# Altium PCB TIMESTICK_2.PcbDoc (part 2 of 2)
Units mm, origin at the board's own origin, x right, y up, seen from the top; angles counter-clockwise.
Board outline 82 x 42 mm, 4 copper layers (Top Layer, Int1, Int2, Bottom Layer), stack 0.954 mm thick; 117 components, 82 nets, 437 pads, 366 vias.
Unrouted connection lines stored in the file: 51.
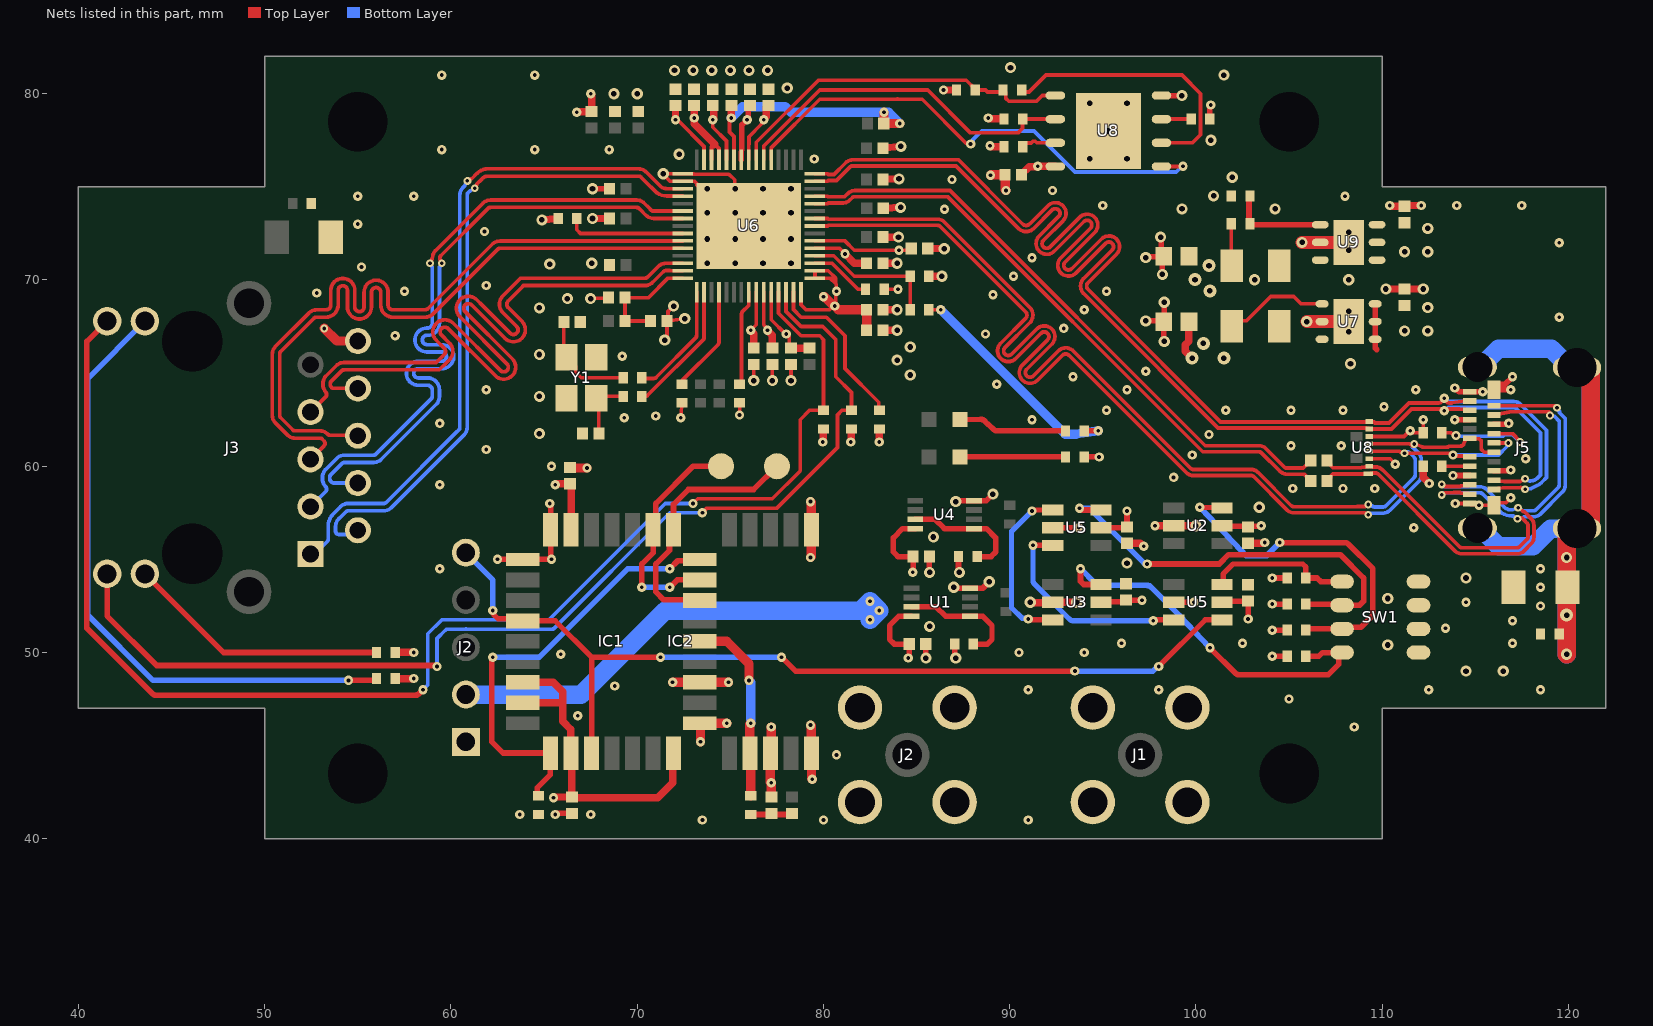
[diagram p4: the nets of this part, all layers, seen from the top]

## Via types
v1: diameter 0.5, hole 0.2, Top Layer to Bottom Layer, tented both sides, 226 vias
v2: diameter 0.6, hole 0.3, Top Layer to Bottom Layer, tented both sides, 105 vias
v3: diameter 0.42, hole 0.2, Top Layer to Bottom Layer, tented both sides, 19 vias
v4: diameter 0.6, hole 0.3, Top Layer to Bottom Layer, 9 vias
v5: diameter 0.7, hole 0.3, Top Layer to Bottom Layer, tented both sides, 7 vias

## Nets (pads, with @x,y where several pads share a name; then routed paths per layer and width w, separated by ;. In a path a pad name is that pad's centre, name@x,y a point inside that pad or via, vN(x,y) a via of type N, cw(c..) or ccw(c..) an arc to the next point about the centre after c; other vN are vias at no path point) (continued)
D_N: J5.A7 J5.B7 U6.38 U8.5@109.3,61.2 | length 58.9
  Top Layer w0.2: U6.38@79.541,72.9 80.215,72.9 80.253,72.937 85.985,72.937 86.12,72.937 cw(c86.12,72.737) 86.261,72.879 87.563,71.577 89.37,69.77 90.17,68.97 90.85,68.29 ; 90.329,65.787 cw(c89.922,66.193) 89.515,65.787 cw(c89.922,66.193) 89.515,66.6 90.851,67.936 ccw(c90.674,68.112) 90.851,68.29 ; 90.33,65.788 91.678,67.137 cw(c91.855,66.96) 92.033,66.784 90.682,65.433 ccw(c91.089,65.027) 90.682,64.62 ccw(c91.089,65.027) 91.496,64.621 ; 91.496,64.621 92.831,65.956 cw(c93.008,65.779) 93.185,65.955 93.37,65.77 99.489,59.652 ccw(c99.858,60.025) 99.858,59.5 102.823,59.5 102.958,59.5 cw(c102.958,59.3) 103.099,59.441 104.887,57.654 ccw(c105.258,58.025) 105.258,57.5 108.785,57.5 108.792,57.507 109.073,57.507 109.19,57.39 v3(109.25,57.39) ; U8.5@109.3,61.2 111.478,61.2 111.608,61.07 v3(111.726,61.187) 111.845,61.147 cw(c111.779,60.958) 111.847,61.146 112.15,61.037 ccw(c112.217,61.225) 112.217,61.025 113.472,61.025 ccw(c113.471,61.225) 113.603,61.075 113.888,61.075 ccw(c113.888,61.275) 113.895,61.075 113.956,61.077 cw(c113.962,60.877) 113.962,61.077 114.191,61.077 ccw(c114.191,61.277) 114.375,61.2 114.479,61.45 J5.A7@114.7,61.5 114.725,61.475 115.2,61.475 115.325,61.35 115.325,60.9 115.475,60.75 J5.B7@116,60.75
  Bottom Layer w0.2: v3(109.25,57.39) 109.277,57.417 109.335,57.475 109.999,57.475 110.087,57.475 110.155,57.498 110.194,57.509 ccw(c110.058,58.016) 110.428,57.643 110.532,57.747 111.947,59.163 ccw(c111.576,59.534) 112.101,59.534 112.101,60.341 ccw(c111.576,60.341) 111.948,60.712 111.71,60.949 ccw(c111.339,60.578) 111.62,61.021 111.726,61.127 v3(111.726,61.187)
D_P: J5.A6 J5.B6 U6.39 U8.4@109.3,60.8 | length 60.1
  Top Layer w0.2: U6.39@79.541,73.3 80.215,73.3 80.253,73.262 86.12,73.262 cw(c86.12,72.737) 86.49,73.11 90.4,69.2 91.081,68.519 ; 91.082,68.518 91.129,68.471 91.129,68.465 cw(c90.674,68.112) 91.081,67.706 89.745,66.37 ccw(c89.922,66.193) 89.745,66.017 ccw(c89.922,66.193) 90.098,66.016 91.449,67.366 cw(c91.855,66.96) 92.208,67.414 92.214,67.414 92.261,67.367 cw(c91.855,66.96) 92.262,67.366 92.309,67.319 92.309,67.313 cw(c91.855,66.96) 92.261,66.553 ; 92.261,66.552 90.912,65.204 ccw(c91.089,65.027) 90.912,64.85 ccw(c91.089,65.027) 91.265,64.849 92.601,66.186 cw(c93.008,65.779) 93.36,66.233 93.367,66.233 93.414,66.186 ; 93.414,66.186 93.6,66 99.717,59.883 ccw(c99.858,60.025) 99.858,59.825 102.958,59.825 cw(c102.958,59.3) 103.329,59.671 105.117,57.883 ccw(c105.258,58.025) 105.258,57.825 108.65,57.825 108.657,57.832 109.073,57.832 109.19,57.95 v3(109.25,57.95) ; U8.4@109.3,60.8 110.933,60.8 110.975,60.757 111.143,60.757 v3@111.21,60.69 ; v3(111.2,60.7) 113.617,60.7 cw(c113.617,60.5) 113.758,60.642 v1(113.8,60.6) 113.848,60.552 114.129,60.552 114.131,60.55 114.65,60.55 J5.A6@114.7,60.5 ; J5.B6@116,61.25 v3(116.775,61.25)
  Bottom Layer w0.2: v3(109.25,57.95) 109.44,57.865 109.447,57.865 109.453,57.859 109.51,57.833 ccw(c109.592,58.016) 109.592,57.816 110.058,57.816 ccw(c110.058,58.016) 110.199,57.874 111.717,59.392 ccw(c111.576,59.534) 111.776,59.534 111.776,59.937 111.776,60.341 ccw(c111.576,60.341) 111.717,60.483 111.481,60.719 ccw(c111.339,60.578) 111.339,60.778 111.262,60.7 v3(111.2,60.7) ; v1(113.8,60.6) 116.25,60.6 116.718,61.068 116.718,61.193 v3(116.775,61.25)
DVDD_1.85: C16.2 C30.2 C31.2 C32.2 FB4.1 U6.26 U6.35 U6.53 U6.56 | length 14.2
  Top Layer w0.2: v1(74.056,78.6) 74.056,78.2 74.791,77.465 U6.56@74.791,76.45 ; U6.53@75.991,76.45 75.991,77.302 75.996,77.307 75.996,77.696 76.661,78.361 76.661,78.38 76.8,78.519 v1(76.8,78.6) ; U6.26@77.191,69.35 77.191,67.865 77.956,67.1 v1(78,67.1) 78,67.093 78.156,66.937 78.156,66.44 C31.2@78.256,66.34 ; U6.35@79.541,71.7 80.856,71.7 v1(81.156,71.4)
  Top Layer w0.4: v1(74.056,78.6) 74.056,78.605 74.117,78.667 74.117,79.299 C16.2@74.056,79.36 ; v1(76.8,78.6) 76.8,78.627 76.938,78.765 76.938,79.26 77.038,79.36 C32.2@77.056,79.36 ; C31.2@78.256,66.34 FB4.1@79.256,66.34 ; v1(81.156,71.4) 81.656,70.9 C30.2@82.316,70.9
DVDD_33: C10.2 C14.2 C19.2 C20.2 C21.2 C22.2 C43.2 C44.2 FB3.1 IC1.7 IC1.8 IC2.2 IC2.7 IC2.23 L1.2 R10.2 R11.2 R14.2@75.5,63.4 R16.1 R17.1 R19.2 R20.2 R21.2 R27.1 R28.1@89.694,78.65 R29.1 R30.1@100.744,78.65 U6.25 U6.36 U6.54 U6.59 U7.1 U8.8@92.45,76.095 | length 59.2
  Top Layer w0.2: v1@71.956,78.7 71.956,79.26 C21.2@72.056,79.36 ; v1(72.056,78.6) 72.156,78.6 72.156,78.56 72.157,78.558 72.198,78.558 73.591,77.165 U6.59@73.591,76.45 ; v1(72.344,62.6) 72.39,63.25 R20.2@72.4,63.4 ; v1(75.494,62.75) 75.499,63.25 R14.2@75.5,63.4 ; U6.25@76.791,69.35 76.791,67.59 77,67.381 v1(77,67.3) ; U6.36@79.541,72.1 81.156,72.1 81.656,71.6 v1(84.056,71.6) 84.616,71.6 C20.2@84.716,71.7 ; R21.2@83.256,69.5 v1(84,69.5) ; L1.2@101.925,67.517 102.216,67.808 102.708,67.808 104.017,69.117 105.25,69.117 105.65,68.717 U7.1@106.775,68.717
  Top Layer w0.3: U6.54@75.591,76.45 75.616,77.41 75.621,77.477 75.621,78.324 75.897,78.6 v1(75.9,78.6) 75.9,78.654 75.959,78.713 75.959,79.263 C22.2@76.056,79.36 ; R30.1@100.744,78.65 100.744,79.312 100.8,79.368 v1(100.8,79.4)
  Top Layer w0.4: R10.2@57,48.6 v1(58,48.6) ; R11.2@57,50 v1(58,50) ; IC1.8@63.85,47.3 66,47.3 ; IC1.7@63.85,48.4 65.5,48.4 66,47.9 66,47.3 ; v1(65.5,42.2) 65.527,42.2 65.567,42.24 C43.2@66.5,42.24 ; v1(65.6,59) 65.627,59 65.687,59.06 C44.2@66.4,59.06 66.45,59.01 IC2.23@66.45,56.6 ; v1(66.75,79) 66.777,79 66.817,79.04 FB3.1@67.556,79.04 67.556,79.917 67.5,79.973 v1(67.5,80) ; IC2.7@71.95,44.6 71.9,44.55 71.9,43 71.1,42.2 66.54,42.2 C43.2@66.5,42.24 ; v1(72.056,78.6) C21.2@72.056,79.36 ; v1(77,67.3) 77,67.273 77.244,67.028 77.244,66.44 77.256,66.429 C19.2@77.256,66.34 ; v1(79.965,61.3) 79.965,61.305 80,61.341 R16.1@80,62 ; v1(81.465,61.3) 81.465,61.305 81.5,61.341 R17.1@81.5,62 ; v1(83,61.3) R19.2@83,62 ; v1(86.444,80.2) R27.1@87.144,80.2 ; v1(88.844,78.7) 88.85,78.7 88.9,78.65 R28.1@89.694,78.65 ; v1(88.944,77.2) 88.95,77.2 89,77.15 R29.1@89.694,77.15 ; C14.2@90.634,75.65 90.634,75.67 91.045,76.081 91.454,76.081 91.468,76.095 U8.8@92.45,76.095 ; C10.2@99.625,67.767 99.625,66.706 99.435,66.516 99.435,66.184 99.8,65.819 v5(99.8,65.8) ; 66,47.3 66,46.3 66.434,45.866 66.434,44.616 66.475,44.575 66.475,42.265 C43.2@66.5,42.24
  other v1: 91.5,76.1
  other v5: 101.5,65.8 100.4,66.6
GND: C1.1 C2.1 C3.1 C4.1 C5.1 C8.1 C9.1 C10.1 C11.1 C12.1 C13.1 C14.1 C15.1 C16.1 C17.1 C18.1 C19.1 C20.1 C21.1 C22.1 C23.1 C24.1 C25.1 C26.1 C27.1 C28.1 C29.1 C30.1 C31.1 C32.1 C33.1 C34.1 C35.1 C36.1 C37.1 C38.1 C39.2 C40.1 C42.1 C43.1 C44.1 IC1.1 IC1.10 IC1.12 IC2.10 IC2.12 IC2.13 IC2.24 J1.2 J1.3 J1.4 J1.5 J2.1@60.8,45.2 J2.2@87.04,41.96 J2.3@81.96,41.96 J2.4@81.96,47.04 J2.5@87.04,47.04 J3.P10 J5.A1 J5.A12 J5.B1 J5.B12 R1.2 R7.1 R12.2 R14.2@64.7,41.3 R15.1 R18.1 R24.1 R28.2@112.2,60 R30.2@112.2,61.8 R33.2 SW1.1 SW1.2 SW1.3 SW1.4 U1.4 U2.2 U3.2 U4.4 U5.2 U6.1 U6.2 U6.61 U7.2 U7.7 U8.4@98.15,79.905 U8.6@109.3,61.6 U8.9@95.3,78 U9.2 U9.7 Y1.2 Y1.4 | length 100
  Top Layer w0.2: v2(67.5,69) C17.1@68.266,69.037 ; C17.1@68.266,69.037 C17.1@68.466,69.05 ; v2(71.481,66.775) 71.56,66.889 ccw(c71.396,67.003) 71.596,67.003 C18.1@71.596,67.8 ; v2(71.956,68.6) 71.659,68.303 71.659,67.863 C18.1@71.596,67.8 ; v2(72.556,67.925) 71.796,67.83 C18.1@71.596,67.8 ; 74.997,75.616 75.231,75.383 75.231,74.9 75.256,74.875 v2(75.256,73.6) 75.291,73.6 U6.61@75.991,72.9 75.409,72.9 73.209,75.1 73.209,75.165 73.074,75.3 71.766,75.3 71.4,75.666 v2(71.4,75.7) 72.988,75.7 ccw(c73.091,75.9) 73.091,75.675 73.291,75.675 74.856,75.675 cw(c74.856,75.475) 74.997,75.617 ; v2(76.256,64.6) C35.1@76.256,65.46 ; v2(77.256,64.6) C19.1@77.256,65.46 ; v2(78.256,64.6) C31.1@78.256,65.46 ; U8.6@109.3,61.6 111.173,61.6 111.473,61.9 111.56,61.9 111.66,61.8 R30.2@112.2,61.8 v1(112.2,62.5) ; v1(113.925,58) J5.A1@114.7,58 114.75,57.95 115.15,57.95 v1(115.2,57.9) J5.B12@116,57.9 116.133,58.033 116.633,58.033 v1(116.9,58.3)
  Top Layer w0.3: v1(62.5,55) IC1.1@63.85,55 v1(65.4,55) 65.4,55.054 65.35,55.104 IC2.24@65.35,56.6 65.35,57.896 65.3,57.946 v1(65.3,58) ; v1(65.6,41.3) 65.654,41.3 65.714,41.36 C43.1@66.5,41.36 ; v2(67.6,74.9) C25.1@68.516,74.9 ; C3.1@85.49,50.45 85.49,49.71 v2(85.5,49.7) ; C5.1@85.69,55.15 85.69,54.31 v2(85.7,54.3) ; v2(87,53.5) 87.05,53.45 U1.4@87.875,53.45 88.55,53.45 v2(88.9,53.8) ; R1.2@87.05,50.45 87.05,49.75 v2(87.1,49.7) ; v2(87.1,58.1) 87.15,58.15 U4.4@88.075,58.15 88.75,58.15 v2(89.1,58.5) ; R7.1@87.25,55.15 87.25,54.35 v2(87.3,54.3) ; U5.2@92.3,56.7 v1(93.7,56.7) ; v2(97.3,67.8) 98.242,67.8 C10.1@98.275,67.767 ; v2(97.3,71.2) 97.339,71.239 98.247,71.239 C28.1@98.275,71.267 ; v2(98.1,72.3) 98.147,72.253 98.147,71.396 C28.1@98.275,71.267 ; U8.4@98.15,79.905 98.155,79.9 v2(99.244,79.9) ; v2(98.2,70.3) 98.2,71.192 C28.1@98.275,71.267 ; v2(98.3,66.7) 98.275,66.725 C10.1@98.275,67.767 ; v2(98.3,68.8) 98.3,68.117 C10.1@98.275,67.767 ; U5.2@98.8,52.7 v1(99.9,52.7) ; v1(113.9,64.2) 113.932,64.2 114.132,64 J5.A12@114.7,64 v1(115.4,64) ; v1(116.9,64.1) J5.B1@116.01,64.1 116.01,64.2 116.21,64.4 116.6,64.4 v1(117,64.8)
  Top Layer w0.4: v2(64.881,73.225) 65.706,73.29 R18.1@65.756,73.3 ; v2(67.6,73.3) C33.1@68.516,73.3 ; C36.1@83.196,67.3 v2(83.956,67.3) ; C37.1@83.196,68.4 v2(83.956,68.4) ; C30.1@83.196,70.9 v2(83.956,70.9) ; C26.1@83.196,72.3 v2(84.031,72.3) ; C12.1@83.196,75.4 83.296,75.403 v2(84.056,75.425) ; C13.1@83.196,77.075 83.296,77.085 v2(84.156,77.175) ; C34.1@83.206,73.85 83.306,73.855 v2(84.141,73.9) ; C20.1@85.596,71.7 85.696,71.697 v2(86.481,71.675) ; R15.1@85.656,70.2 v2(86.356,70.2) ; v2(91.1,52.7) 91.132,52.668 91.993,52.668 92.025,52.7 v2(93.6,52.7) ; C4.1@96.3,55.86 97.013,55.86 97.173,55.7 v1(97.2,55.7) ; v1(97.8,56.8) 98.425,56.8 v2(100,56.8) ; C1.1@102.8,55.86 103.633,55.86 103.673,55.9 v1(103.7,55.9) ; v2(110.2,69.517) v2(112.2,69.517) ; v1(110.4,74) 110.427,74 110.47,73.957 C29.1@111.2,73.957 111.243,74 v1(112.1,74) ; R28.2@112.2,60 112.2,59.4 v1(112.525,59.075)
  Top Layer w0.5: v3(53.2,67.4) 53.88,66.72 J3.P10@55,66.72 ; C44.1@66.4,59.94 66.44,59.9 v1(67.3,59.9) ; v1(71.9,48.4) IC1.12@73.35,48.4 v1(74.9,48.4) ; IC1.10@73.35,46.2 73.4,46.15 v1(73.4,45.2) ; IC1.10@73.6,46.2 v1(74.8,46.2) ; C42.1@77.2,42.24 v1(77.2,43) 77.15,43.05 IC2.10@77.15,44.6 77.2,44.65 v1(77.2,46) ; v1(79.3,46.1) 79.35,46.05 IC2.12@79.35,44.6 79.355,44.595 79.355,43.245 v1(79.4,43.2) ; v1(79.3,55.1) 79.35,55.15 IC2.13@79.35,56.6 79.35,58.05 v1(79.3,58.1) ; v1(88.969,75.625) 88.994,75.65 C14.1@89.754,75.65 89.754,74.846 v1(89.8,74.8)
  Top Layer w0.7: v2(105.7,72.017) U9.2@106.675,72.017 U9.7@108.2,72.017 ; v2(105.95,67.767) U7.2@106.775,67.767 U7.7@108.2,67.767
  other v1: 73.5,41 80,41 91,41 63.7,41.3 67.5,41.3 80.7,44.5 108.5,46 66.8,46.6 105,47.5 91,48 98,48 112.5,48 118.5,48 68.8,48.2 65.9,49.9 90.5,50 94,50 96,50.5 102.5,50.5 117,50.5 113.4,51.3 117,51.7 118.5,52.5 114.5,52.7 118.5,53.5 59.4,54.5 118.5,54.5 111.7,56.7 105.2,58.8 107.9,58.8 109.6,58.8 59.4,59 98.8,59.4 65.4,60 117.7,60.4 99.8,60.6 61.9,60.9 105.1,61.1 107.8,61.1 100.7,61.7 111.5,61.9 59.4,62.3 91.2,62.5 69.3,62.6 71,62.7 95.2,63 101.6,63 105.1,63 107.9,63 110.1,63.2 61.9,64.1 96.3,64.1 111.8,64.1 89.3,64.4 93.4,64.8 97.3,65.1 69.2,65.9 57,67 88.7,67.1 92.9,67.4 119.5,68 94,68.4 89.1,69.2 52.8,69.3 57.5,69.4 95.2,69.4 61.9,69.7 90.2,70.2 55.2,70.7 91.2,71.2 119.5,72 61.8,72.6 55,73 86.5,73.8 95,74 114,74 117.5,74 55,74.5 58,74.5 108,74.5 92.3,74.8 86.9,75.4 79.5,76.5 59.5,77 64.5,77 68.5,77 59.5,81 64.5,81
  other v2: 114.5,49 116.5,49 110.3,50.4 85.7,51.4 110.3,52.9 114.5,54 96.3,54.8 85.9,56.2 103.4,57.8 64.75,61.75 64.75,63.75 108.3,65.5 64.75,66 64.75,68.5 66.25,69 103.15,70.017 108.2,70.017 65.306,70.85 67.556,70.9 73.756,70.9 75.256,70.9 76.756,70.9 78.256,70.9 73.756,72.2 75.256,72.2 76.756,72.2 78.256,72.2 73.756,73.6 76.756,73.6 78.256,73.6 99.25,73.817 104.25,73.817 100.95,74.517 73.756,74.9 75.256,74.9 76.756,74.9 78.256,74.9 101.95,75.517 72.25,76.75 100.8,77.5 68.75,80 70,80 78.056,80.3 101.5,81 72,81.25 73,81.25 74,81.25 75,81.25 76,81.25 77,81.25 90.044,81.4
  other v4: 108.2,67.217 108.2,68.317 108.2,71.6 108.2,72.567 94.3,76.5 96.3,76.5 95.3,78 94.3,79.5 96.3,79.5
GPS_PPS_OUT: IC1.4 IC2.3 J2.5@60.8,55.36 U5.4@101.4,51.75 | length 50.6
  Top Layer w0.286: v1(62.25,52.25) 62.291,52.209 62.291,52.045 62.525,51.812 63.738,51.812 IC1.4@63.85,51.7 65.6,51.7 67.55,49.75 ; IC2.3@67.55,44.6 67.55,49.75 ; v1(71.25,49.75) 67.55,49.75 ; v1(77.75,49.75) 78.5,49 v1(93.5,49) ; v1(98,49.25) 100.5,51.75 U5.4@101.4,51.75
  Bottom Layer w0.286: J2.5@60.8,55.34 62.25,53.89 v1(62.25,52.25) ; v1(71.25,49.75) v1(77.75,49.75) ; v1(93.5,49) 97.692,49 97.942,49.25 v1(98,49.25)
LED0: J3.P12 R16.2 U6.27 | length 75.4
  Top Layer w0.2: v1(73,58) 73.25,58.25 77.25,58.25 78.75,59.75 78.75,62.5 79.25,63 R16.2@80,63 80,66.796 79.796,67 78.8,67 77.591,68.209 U6.27@77.591,69.35
  Top Layer w0.3: J3.P12@41.54,67.79 40.45,66.7 40.45,51.3 43.962,47.788 ccw(c44.174,48) 44.174,47.7 58.076,47.7 ccw(c58.076,48) 58.287,47.787 v1(58.5,48)
  Bottom Layer w0.2: v1(58.5,48) 58.75,48.25 58.75,51 59.5,51.75 65.25,51.75 71.5,58 v1(73,58)
LED1: J3.P14 R17.2 U6.28 | length 59.4
  Top Layer w0.2: v1(73.5,57.5) 73.75,57.75 77.5,57.75 80.75,61 80.75,62.75 81,63 R17.2@81.5,63 81.5,63.956 80.656,64.8 80.656,66.8 79.956,67.5 78.8,67.5 77.991,68.309 U6.28@77.991,69.35
  Top Layer w0.3: J3.P14@41.54,54.22 41.54,51.96 44.2,49.3 59.115,49.3 59.142,49.273 59.227,49.273 v1(59.25,49.25)
  Bottom Layer w0.2: v1(59.25,49.25) 59.25,50.75 59.691,51.191 cw(c59.833,51.05) 59.832,51.25 60.795,51.255 cw(c60.8,50.28) 60.801,51.255 65.417,51.25 ccw(c65.417,51.45) 65.559,51.309 71.75,57.5 v1(73.5,57.5)
MDI0_N: J3.P2 U6.4 | length 36
  Top Layer w0.2: v3(61.275,74.925) 61.275,74.985 61.389,75.099 61.389,75.156 61.634,75.401 61.679,75.446 cw(c61.988,75.139) 61.989,75.575 70.067,75.575 cw(c70.067,75.375) 70.208,75.517 70.323,75.403 70.489,75.239 70.954,74.774 ccw(c71.6,75.42) 71.6,74.506 U6.4@72.435,74.506
  Bottom Layer w0.2: 53.959,57.159 ccw(c54.341,56.776) 53.8,56.777 53.8,56.53 ccw(c54,56.53) 54,56.33 54.688,56.33 ccw(c54.688,56.53) 54.829,56.389 J3.P2@55,56.56 ; 53.959,57.159 54.144,57.344 54.348,57.548 cw(c54.489,57.406) 54.489,57.606 56.385,57.606 ccw(c56.385,58.2) 56.804,57.779 60.695,61.67 ccw(c60.275,62.09) 60.869,62.089 60.869,73.637 60.869,74.554 cw(c61.069,74.554) 60.927,74.695 60.987,74.754 cw(c61.128,74.613) 61.017,74.779 61.189,74.893 cw(c61.3,74.727) v3(61.275,74.925)
MDI0_P: J3.P1 U6.3 | length 37
  Top Layer w0.2: v3(60.879,75.321) 60.939,75.321 61.053,75.435 61.11,75.435 61.401,75.726 cw(c61.988,75.139) 61.99,75.969 70.067,75.969 cw(c70.067,75.375) 70.449,75.83 70.477,75.806 cw(c70.349,75.653) 70.488,75.796 70.49,75.795 71.211,75.074 71.233,75.052 ccw(c71.6,75.42) 71.6,74.9 71.991,74.9 U6.3@72.441,74.9
  Bottom Layer w0.2: J3.P1@52.46,55.29 53.06,55.66 53.348,55.948 ccw(c53.206,56.089) 53.406,56.089 53.406,56.777 cw(c54.341,56.776) 53.681,57.438 53.695,57.453 54.07,57.827 cw(c54.489,57.406) 54.489,58 56.385,58 ccw(c56.385,58.2) 56.526,58.058 60.301,61.833 60.417,61.949 ccw(c60.275,62.09) 60.475,62.089 60.475,73.637 60.475,73.834 60.475,74.554 cw(c61.069,74.554) 60.648,74.973 60.709,75.034 ccw(c60.567,75.174) 60.733,75.064 60.847,75.235 ccw(c60.681,75.346) v3(60.879,75.321)
MDI1_N: J3.P4 U6.7 | length 36
  Top Layer w0.2: v3(59.5,70.9) ccw(c59.304,70.858) 59.483,70.947 59.419,71.077 cw(c59.598,71.166) 59.457,71.307 61.992,73.842 cw(c62.133,73.7) 62.133,73.9 69.96,73.9 cw(c69.96,73.7) 70.101,73.842 70.217,73.726 70.463,73.48 ccw(c70.883,73.9) 70.883,73.306 U6.7@72.435,73.306
  Bottom Layer w0.2: J3.P4@55,59.1 53.719,59.1 cw(c53.719,59.3) 53.578,59.158 53.552,59.185 cw(c53.694,59.325) 53.494,59.325 53.494,59.411 cw(c53.694,59.411) 53.552,59.552 54.142,60.142 cw(c54.283,60) 54.283,60.2 55.836,60.2 ccw(c55.836,60.794) 56.255,60.373 59.212,63.329 ccw(c58.79,63.748) 59.385,63.748 59.385,63.8 59.385,64.097 ccw(c58.74,64.097) 58.74,64.741 58.249,64.741 cw(c58.249,64.991) 58.249,65.241 59.506,65.241 ccw(c59.506,65.885) 59.506,66.529 58.707,66.529 cw(c58.707,66.779) 58.707,67.029 58.74,67.029 ccw(c58.74,67.673) 59.385,67.673 59.385,68.6 59.385,70.703 59.5,70.819 v3(59.5,70.9)
MDI1_P: J3.P3 U6.6 | length 37
  Top Layer w0.2: v3(58.875,70.9) cw(c59.071,70.858) 58.895,70.955 58.966,71.083 ccw(c58.79,71.18) 58.986,71.139 59.017,71.286 cw(c59.598,71.166) 59.177,71.585 61.714,74.121 cw(c62.133,73.7) 62.133,74.294 69.96,74.294 cw(c69.96,73.7) 70.38,74.12 70.626,73.874 70.742,73.758 ccw(c70.883,73.9) 70.883,73.7 U6.6@72.441,73.7
  Bottom Layer w0.2: J3.P3@52.46,57.83 53.264,58.634 ccw(c53.122,58.775) 53.269,58.911 53.258,58.922 cw(c53.694,59.325) 53.1,59.325 53.1,59.411 cw(c53.694,59.411) 53.274,59.831 53.864,60.421 cw(c54.283,60) 54.283,60.594 55.836,60.594 ccw(c55.836,60.794) 55.977,60.652 58.932,63.607 ccw(c58.79,63.748) 58.99,63.748 58.99,63.8 58.99,64.097 ccw(c58.74,64.097) 58.74,64.347 58.249,64.347 cw(c58.249,64.991) 58.249,65.635 59.506,65.635 ccw(c59.506,65.885) 59.506,66.135 58.707,66.135 cw(c58.707,66.779) 58.707,67.423 58.74,67.423 ccw(c58.74,67.673) 58.99,67.673 58.99,68.6 58.99,70.703 58.875,70.819 v3(58.875,70.9)
MDI2_N: J3.P6 U6.11 | length 37.1
  Top Layer w0.2: J3.P6@55,61.64 ccw(c54.901,61.466) 54.902,61.666 53.516,61.666 cw(c53.516,61.866) 53.375,61.725 ccw(c52.954,61.306) 52.954,61.9 51.64,61.9 cw(c51.64,62.1) 51.499,61.958 50.858,62.599 cw(c51,62.74) 50.8,62.74 50.8,66.017 cw(c51,66.017) 50.858,66.158 52.648,67.948 cw(c52.789,67.806) 52.789,68.006 53,68.006 53.297,68.006 ccw(c53.297,68.65) 53.941,68.65 53.941,69.441 cw(c54.191,69.441) 54.441,69.441 54.441,68.55 ccw(c55.085,68.55) 55.729,68.55 55.729,69.345 cw(c55.979,69.345) 56.229,69.345 56.229,68.65 ccw(c56.873,68.65) 56.873,68.006 57.8,68.006 58.617,68.006 ccw(c58.617,68.6) 59.036,68.179 62.499,71.642 cw(c62.64,71.5) 62.64,71.7 U6.11@72.441,71.7
MDI2_P: J3.P5 U6.10 | length 37.8
  Top Layer w0.2: J3.P5@52.46,60.37 52.69,60.6 53.176,61.086 ccw(c53.034,61.227) 53.175,61.369 53.094,61.449 ccw(c52.954,61.306) 52.954,61.506 52.64,61.506 51.64,61.506 cw(c51.64,62.1) 51.222,61.678 50.578,62.322 cw(c51,62.74) 50.406,62.74 50.406,66.017 cw(c51,66.017) 50.579,66.436 52.37,68.227 cw(c52.789,67.806) 52.789,68.4 53,68.4 53.297,68.4 ccw(c53.297,68.65) 53.547,68.65 53.547,69.441 cw(c54.191,69.441) 54.835,69.441 54.835,68.55 ccw(c55.085,68.55) 55.335,68.55 55.335,69.345 cw(c55.979,69.345) 56.623,69.345 56.623,68.65 ccw(c56.873,68.65) 56.873,68.4 57.8,68.4 58.617,68.4 ccw(c58.617,68.6) 58.758,68.458 62.221,71.921 cw(c62.64,71.5) 62.64,72.094 U6.10@72.435,72.094
MDI3_N: J3.P8 U6.14 | length 37
  Top Layer w0.2: J3.P8@55,64.18 53.719,64.18 cw(c53.719,64.38) 53.519,64.38 53.519,64.437 cw(c53.719,64.437) 53.578,64.578 54.117,65.117 cw(c54.258,64.975) 54.258,65.175 59.375,65.175 59.7,65.5 59.91,65.71 ccw(c59.455,66.165) 59.968,66.555 59.968,66.563 59.911,66.62 ; 59.845,67.393 ccw(c59.668,67.216) 59.491,67.393 ccw(c59.668,67.216) 59.491,67.04 59.91,66.621 ; 59.846,67.392 62.374,64.864 ; 61.11,68.657 62.897,66.87 ccw(c63.352,67.325) 63.806,66.869 63.807,66.87 ccw(c63.352,67.325) 63.807,67.781 63.071,68.517 cw(c63.248,68.694) 63.071,68.871 63.75,69.55 63.9,69.7 70.403,69.7 ccw(c70.403,70.314) 70.412,69.7 ccw(c70.403,70.314) 70.837,69.88 71.401,70.444 71.405,70.448 cw(c71.543,70.303) 71.543,70.503 71.732,70.503 cw(c71.732,70.303) 71.734,70.503 71.991,70.5 U6.14@72.441,70.5 ; 61.109,68.657 ccw(c60.932,68.481) 60.755,68.658 ccw(c60.932,68.481) 60.755,68.304 63.343,65.716 63.343,65.708 cw(c62.83,65.318) 63.286,64.863 63.284,64.862 cw(c62.83,65.318) 62.374,64.864
MDI3_P: J3.P7 U6.13 | length 37.8
  Top Layer w0.2: J3.P7@52.46,62.91 53.265,63.715 ccw(c53.123,63.856) 53.274,63.987 cw(c53.719,64.38) 53.125,64.38 53.125,64.437 cw(c53.719,64.437) 53.299,64.857 53.572,65.13 53.838,65.395 cw(c54.258,64.975) 54.258,65.569 59.212,65.569 59.421,65.779 59.631,65.989 ccw(c59.455,66.165) 59.631,66.343 ; 59.63,66.343 59.213,66.76 cw(c59.668,67.216) 59.211,67.671 59.213,67.672 cw(c59.668,67.216) 60.057,67.73 60.066,67.73 62.654,65.141 ccw(c62.83,65.318) 63.007,65.142 ccw(c62.83,65.318) 63.007,65.496 ; 63.006,65.496 60.478,68.024 cw(c60.932,68.481) 60.476,68.935 60.477,68.936 cw(c60.932,68.481) 61.321,68.994 61.33,68.994 61.749,68.575 63.175,67.149 ccw(c63.352,67.325) 63.529,67.149 ccw(c63.352,67.325) 63.529,67.502 62.792,68.239 cw(c63.248,68.694) 62.792,69.149 63.471,69.829 63.737,70.094 70.403,70.094 ccw(c70.403,70.314) 70.559,70.159 70.668,70.268 71.124,70.724 cw(c71.543,70.303) 71.543,70.897 71.764,70.897 71.767,70.9 U6.13@72.441,70.9
MUX1_CTRL: R3.1 SW1.8 U3.6 | length 21
  Top Layer w0.3: v1(93.8,54.5) 93.8,53.826 93.976,53.65 U3.6@94.9,53.65 ; v1(100.75,50.25) 102.113,48.887 ccw(c102.324,49.1) 102.323,48.8 107.1,48.8 107.658,49.358 107.658,49.803 SW1.8@107.85,49.995 106.795,49.995 106.6,49.8 R3.1@105.9,49.8
  Bottom Layer w0.3: v1(93.8,54.5) 94.612,53.688 ; 94.613,53.687 ccw(c94.824,53.9) 94.824,53.6 97.376,53.6 cw(c97.376,53.3) 97.588,53.512 99.097,52.003 cw(c98.885,51.791) 99.103,51.997 v1(100.75,50.25)
MUX2_CTRL: R4.1 SW1.7 U2.6 | length 18.9
  Top Layer w0.3: v1(100.2,57.8) 100.975,57.768 U2.6@101.4,57.75 ; v1(104.5,55.9) 107.976,55.9 cw(c107.976,55.6) 108.188,55.812 109.5,54.5 109.5,52 108.847,51.347 107.932,51.347 SW1.7@107.85,51.265 105.965,51.265 R4.1@105.9,51.2
  Bottom Layer w0.3: v1(100.2,57.8) 102.499,55.401 ccw(c102.714,55.61) 102.501,55.399 102.502,55.398 102.7,55.2 103.8,55.2 v1(104.5,55.9)
MUX3_CTRL: R5.1 SW1.6 U5.6@94.9,57.65 | length 22.9
  Top Layer w0.3: v1(93.75,57.75) 93.782,57.75 93.882,57.65 U5.6@94.9,57.65 ; v1(97.377,54.75) 101.25,54.75 101.75,55.25 107.75,55.25 109,54 109,52.75 108.785,52.535 SW1.6@107.85,52.535 107.785,52.6 R5.1@105.9,52.6
  Bottom Layer w0.3: v1(93.75,57.75) 94.25,57.75 97.227,54.773 97.354,54.773 v1(97.377,54.75)
MUX4_CTRL: R6.1@105.9,54 SW1.5 U5.6@101.4,53.65 | length 7.9
  Top Layer w0.286: U5.6@101.4,53.65 101.462,53.712 101.462,54.212 102,54.75 105.732,54.75 105.9,54.582 R6.1@105.9,54
  Top Layer w0.3: R6.1@105.9,54 106.5,54 106.7,53.8 107.845,53.8 SW1.5@107.85,53.805
NetC8_2: C8.2 R25.1 Y1.1 | length 3.4
  Top Layer w0.2: C8.2@67.94,61.75 67.94,63.51 Y1.1@67.8,63.65 68.3,63.75 R25.1@69.25,63.75
NetC9_2: C9.2 R26.1 Y1.3 | length 5.6
  Top Layer w0.2: C9.2@66.06,67.75 66.06,65.99 Y1.3@66.2,65.85 66.7,65.35 66.7,65.05 67,64.75 R26.1@69.25,64.75
NetC17_2: C17.2 C18.2 FB2.1 U6.15 | length 6.2
  Top Layer w0.2: C18.2@70.716,67.8 FB2.1@69.346,67.8 C17.2@69.346,69.05 70.606,69.05 71.656,70.1 U6.15@72.441,70.1
NetC40_2: C40.2 J5.S R24.2 | length 47.1
  Top Layer w0.2: v5@119.9,51.8 v5(119.9,52)
  Top Layer w1: v2(119.9,49.9) v5@119.9,51.8 ; v5(119.9,52) v2(119.9,55.1) 119.9,56.614 119.946,56.66 J5.S@120.46,56.66 121.154,56.66 121.2,56.706 121.2,65.254 121.154,65.3 J5.S@120.46,65.3
  Bottom Layer w1: J5.S@115.11,56.68 115.583,56.68 115.629,56.634 115.629,56.317 116.246,55.7 118.1,55.7 119.041,56.641 J5.S@119.927,56.641 ; J5.S@115.11,65.32 115.583,65.32 115.629,65.366 115.629,65.683 116.246,66.3 119.074,66.3 119.691,65.683 119.691,65.346 119.737,65.3 121.154,65.3 121.2,65.254 121.2,56.706 121.154,56.66 J5.S@120.46,56.66 120.441,56.641 J5.S@119.927,56.641 ; v2(119.9,49.9) v5(119.9,52) v2(119.9,55.1) 119.9,56.614 J5.S@119.927,56.641
NetC42_2: C42.2 FB5.1 R38.2 | length 2.2
  Top Layer w0.3: R38.2@76.1,41.3 78.24,41.3 FB5.1@78.3,41.36
NetD1_2: D1.2 R2.1 | length 5.9
  Top Layer w0.3: D1.2@87.325,62.5 88.443,62.517 ; 88.444,62.517 cw(c88.448,62.217) 88.657,62.433 89.119,61.985 ccw(c89.328,62.2) 89.328,61.9 R2.1@93,61.9
NetD2_2: D2.2 R8.1 | length 5.7
  Top Layer w0.3: D2.2@87.325,60.5 R8.1@93,60.5
NetJ3_P11: J3.P11 R10.1 | length 34.1
  Top Layer w0.3: v1(54.5,48.5) 55.9,48.5 R10.1@56,48.6
  Bottom Layer w0.3: J3.P11@43.57,67.79 40.5,64.72 40.5,52 44,48.5 v1(54.5,48.5)
NetJ3_P13: J3.P13 R11.1 | length 14.2
  Top Layer w0.3: J3.P13@43.57,54.22 47.79,50 R11.1@56,50
NetJ5_A5: J5.A5 R28.1@113.2,60 | length 1.5
  Top Layer w0.2: R28.1@113.2,60 113.35,60 J5.A5@114.7,60
NetJ5_B5: J5.B5 R30.1@113.2,61.8 | length 6.1
  Top Layer w0.2: R30.1@113.2,61.8 113.7,61.8 113.845,61.655 v1(113.958,61.655) ; J5.B5@116,61.75 116.99,61.75 117.4,61.34 v3(117.4,61.3)
  Bottom Layer w0.2: v1(113.958,61.655) 114,61.612 116.501,61.612 116.589,61.7 117,61.7 v3(117.4,61.3)
NetL1_1: L1.1 U7.3
NetL2_1: L2.1 U9.3
NetR1_1: R1.1 U1.1 U1.7 | length 6.6
  Top Layer w0.286: U1.7@84.725,52.45 86.05,52.45 86.55,51.95 U1.1@87.875,51.95 88.55,51.95 89.05,51.45 89.05,50.7 88.8,50.45 R1.1@88.05,50.45
NetR7_2: R7.2 U4.1 U4.7 | length 6.6
  Top Layer w0.3: U4.7@84.925,57.15 86,57.15 86.5,56.65 U4.1@88.075,56.65 88.75,56.65 89.25,56.15 89.25,55.4 89,55.15 R7.2@88.25,55.15
NetR18_2: R18.2 U6.9 | length 6.4
  Top Layer w0.2: R18.2@66.756,73.3 66.756,72.7 66.956,72.5 71.932,72.5 U6.9@72.441,72.5
NetR19_1: R19.1 U6.29 | length 9.1
  Top Layer w0.2: U6.29@78.391,69.35 78.391,68.409 78.8,68 80.156,68 81.156,67 81.156,65.244 82.967,63.433 82.967,63.033 R19.1@83,63
NetR20_1: R20.1 U6.19 | length 5.8
  Top Layer w0.2: R20.1@72.4,64.4 72.389,64.55 cw(c72.58,64.491) 72.438,64.632 74.333,66.527 ccw(c74.191,66.668) 74.391,66.668 U6.19@74.391,69.35
NetR21_1: R21.1 U6.33 | length 3.3
  Top Layer w0.2: U6.33@79.541,70.9 80.456,70.9 81.856,69.5 R21.1@82.256,69.5
NetR29_2: R29.2 U8.7@92.45,77.365 | length 1.9
  Top Layer w0.2: R29.2@90.694,77.15 90.694,77.2 90.844,77.35 91.145,77.35 91.245,77.45 91.365,77.45 91.45,77.365 U8.7@92.45,77.365
NetR30_2: R30.2@99.744,78.65 U8.3@98.15,78.635 | length 1.6
  Top Layer w0.203: U8.3@98.15,78.635 98.165,78.65 R30.2@99.744,78.65
NetR31_1: R31.1 U8.2@98.15,77.365 | length 14.9
  Top Layer w0.203: R31.1@90.644,80.2 90.744,80.1 91.044,80.1 91.944,81 99.244,81 100.244,80 100.244,77.8 99.809,77.365 99.065,77.365 U8.2@98.15,77.365
NetR32_2: R32.2 R33.1 U9.1 | length 5.3
  Top Layer w0.3: R33.1@102.9,74.517 102.85,74.467 102.85,73.067 102.95,72.967 U9.1@106.675,72.967
NetU3_3: U3.3 U5.1@92.3,57.65 | length 9.2
  Top Layer w0.286: v1(91,51.8) 91.058,51.8 91.108,51.75 U3.3@92.3,51.75 ; v1(91.2,57.6) 91.258,57.6 91.308,57.65 U5.1@92.3,57.65
  Bottom Layer w0.286: v1(91,51.8) 90.959,51.841 90.659,51.841 90.1,52.4 90.1,56.5 v1(91.2,57.6)
NetU5_3: U5.3 | length 11.4
  Top Layer w0.286: v1(91.25,55.75) U5.3@92.3,55.75 ; v1(97.7,51.7) 97.758,51.7 97.808,51.75 U5.3@98.8,51.75
  Bottom Layer w0.286: v1(91.25,55.75) 91.25,53.868 ccw(c91.536,53.868) 91.333,53.667 93.217,51.783 ccw(c93.418,51.986) 93.418,51.7 v1(97.7,51.7)
RESET_N: R14.1@75.5,64.4 U6.23 | length 5.1
  Top Layer w0.203: R14.1@75.5,64.4 75.6,64.548 75.6,68.16 cw(c75.803,68.16) 75.659,68.304 75.991,68.635 U6.23@75.991,69.35
SB: IC1.18 IC2.1 R14.1@64.7,42.3 | length 23.9
  Top Layer w0.3: v1(62.25,49.75) 62.227,49.727 62.227,49.642 62.2,49.615 62.2,45.2 62.8,44.6 IC2.1@65.35,44.6 65.326,44.576 65.326,43.426 64.643,42.743 64.643,42.357 R14.1@64.7,42.3 ; v1(71.75,54.5) 72.176,54.926 73.276,54.926 IC1.18@73.35,55
  Bottom Layer w0.3: v1(62.25,49.75) 64.75,49.75 69.5,54.5 v1(71.75,54.5)
SCL: IC1.17 IC2.19 TP2.1 | length 12.4
  Top Layer w0.3: v1(70.25,53.5) 70.25,54.75 70.85,55.35 IC2.19@70.85,56.6 71,56.75 71,58 73,60 TP2.1@74.5,60 ; v1(71.75,53.5) 72.15,53.9 IC1.17@73.35,53.9
  Bottom Layer w0.3: v1(70.25,53.5) v1(71.75,53.5)
SDA: IC1.16 IC2.18 TP1.1 | length 14
  Top Layer w0.3: IC1.16@73.35,52.8 73.326,52.824 71.426,52.824 71,53.25 71,54.75 71.732,55.482 71.732,56.382 IC2.18@71.95,56.6 71.95,57.95 72.75,58.75 76.25,58.75 TP1.1@77.5,60
SPI_CLK: R28.2@90.694,78.65 U6.51 U8.6@92.45,78.635 | length 19.2
  Top Layer w0.203: U6.51@76.791,76.45 76.791,77.191 79.8,80.2 85.6,80.2 87.9,77.9 90.444,77.9 90.694,78.15 R28.2@90.694,78.65 92.435,78.65 U8.6@92.45,78.635
SPI_CS: U6.50 U8.1@98.15,76.095 | length 27.4
  Top Layer w0.203: U6.50@77.191,76.45 77.191,77.091 79.8,79.7 84,79.7 ; 83.975,79.725 84,79.7 ; v1(87.9,77.3) 87.858,77.342 87.658,77.342 85.3,79.7 84,79.7 ; U8.1@98.15,76.095 v1@99.349,76.095
  Bottom Layer w0.203: v1(87.9,77.3) 87.9,77.359 88.036,77.495 88.036,77.536 88.5,78 91.3,78 93.5,75.8 98.941,75.8 99.241,76.1 v1(99.3,76.1)
SPI_DIO: R27.2 R31.2 U6.52 U8.5@92.45,79.905 | length 19.3
  Top Layer w0.203: U6.52@76.391,76.45 76.391,77.391 79.726,80.726 87.668,80.726 88.144,80.25 R27.2@88.144,80.2 88.146,80.202 88.699,80.202 88.8,80.1 89.544,80.1 R31.2@89.644,80.2 89.793,80.051 89.793,79.751 89.944,79.6 91.444,79.6 91.749,79.905 U8.5@92.45,79.905
SSRX_N: J5.A10 J5.B10 U6.44 U8.7@109.3,62 | length 67.2
  Top Layer w0.2: U6.44@79.541,75.3 80.215,75.3 80.253,75.337 80.697,75.337 81.426,76.067 cw(c81.567,75.925) 81.567,76.125 87.115,76.125 90.286,72.954 90.471,72.769 ccw(c90.879,73.175) 91.285,72.768 92.272,73.755 cw(c92.45,73.579) 92.626,73.756 cw(c92.45,73.579) 92.626,73.402 91.534,72.31 91.534,72.304 ccw(c91.988,71.951) 92.395,71.545 93.981,73.13 ; 93.981,73.131 cw(c94.159,72.955) 94.335,73.131 cw(c94.159,72.955) 94.335,72.778 92.701,71.143 92.701,71.137 ccw(c93.155,70.784) 93.562,70.378 95.147,71.964 ; 95.148,71.964 cw(c95.325,71.788) 95.502,71.965 cw(c95.325,71.788) 95.502,71.611 93.972,70.081 ccw(c94.379,69.675) 93.973,69.267 94.802,68.438 101.185,62.055 109.002,62.055 109.007,62.05 109.125,62.05 109.15,62.025 109.275,62.025 U8.7@109.3,62 110.5,62 111.575,63.075 113.165,63.075 113.265,62.975 v1(113.325,62.975) ; v1@113.325,63.075 114.129,63.075 cw(c114.129,62.875) 114.145,63.074 114.45,63.05 J5.A10@114.7,63 ; J5.B10@116,59.25 116.25,59.2 116.556,59.176 ccw(c116.571,59.375) 116.57,59.175 117.342,59.175 ccw(c117.342,59.375) 117.436,59.198 v3(117.675,59.325)
  Bottom Layer w0.2: v1(113.325,62.975) 113.38,62.975 113.552,63.147 116.935,63.147 117.07,63.147 cw(c117.07,62.947) 117.211,63.089 118.5,61.8 118.5,59.525 118.34,59.365 cw(c117.965,59.741) 117.768,59.248 cw(c117.843,59.433) v3(117.675,59.325)
SSRX_P: J5.A11 J5.B11 U6.45 U8.8@109.3,62.4 | length 68.5
  Top Layer w0.2: U6.45@79.541,75.7 80.215,75.7 80.253,75.662 80.562,75.662 81.196,76.296 81.198,76.298 cw(c81.567,75.925) 81.567,76.45 87.25,76.45 90.516,73.184 90.702,72.998 ccw(c90.879,73.175) 91.055,72.998 92.091,74.033 92.097,74.033 cw(c92.45,73.579) 92.856,73.986 cw(c92.45,73.579) 92.857,73.174 91.812,72.129 ccw(c91.988,71.951) 91.811,71.774 ccw(c91.988,71.951) 92.165,71.774 93.8,73.409 93.806,73.409 cw(c94.159,72.955) 94.565,73.361 cw(c94.159,72.955) 94.566,72.549 92.979,70.962 ; 92.979,70.961 ccw(c93.155,70.784) 92.978,70.608 ccw(c93.155,70.784) 93.332,70.608 94.966,72.242 94.973,72.242 cw(c95.325,71.788) 95.732,72.195 cw(c95.325,71.788) 95.733,71.382 94.202,69.852 ccw(c94.379,69.675) 94.202,69.498 95.032,68.668 101.32,62.38 109.28,62.38 U8.8@109.3,62.4 109.325,62.375 109.568,62.375 109.618,62.325 110.365,62.325 111.44,63.4 113.038,63.4 ccw(c113.038,63.6) 113.196,63.478 113.32,63.639 v1(113.325,63.645) 113.403,63.638 ccw(c113.6,63.601) 113.6,63.4 113.716,63.4 114.651,63.537 J5.A11@114.7,63.5 ; J5.B11@116,58.75 116.25,58.8 116.481,58.846 cw(c116.52,58.65) 116.519,58.85 117.342,58.85 ccw(c117.342,59.375) 117.355,58.85 117.436,58.852 cw(c117.445,58.505) v3@117.674,58.766
  Bottom Layer w0.2: v1(113.325,63.645) 113.38,63.645 113.552,63.472 117.07,63.472 cw(c117.07,62.947) 117.44,63.32 118.825,61.935 118.825,59.39 118.571,59.137 cw(c117.965,59.741) 118.345,58.974 118.025,58.815 cw(c117.937,58.995) 117.944,58.795 117.759,58.788 ccw(c117.768,58.588) v3(117.675,58.765)
SSTX_N: C6.2 U6.41 | length 33.1
  Top Layer w0.2: U6.41@79.541,74.1 80.215,74.1 80.253,74.137 81.045,74.137 ccw(c81.045,74.662) 81.416,74.291 81.542,74.417 cw(c81.683,74.275) 81.683,74.475 86.665,74.475 100.175,60.965 100.365,60.775 103.383,60.775 cw(c103.383,60.575) 103.524,60.717 104.513,59.727 ccw(c104.883,60.1) 104.883,59.575 105.805,59.575 106.16,59.22 C6.2@106.16,59.2
SSTX_P: C7.2 U6.42 | length 33.1
  Top Layer w0.2: U6.42@79.541,74.5 80.215,74.5 80.253,74.462 81.045,74.462 ccw(c81.045,74.662) 81.187,74.522 81.312,74.647 cw(c81.683,74.275) 81.683,74.8 86.283,74.8 86.8,74.8 100.5,61.1 103.383,61.1 cw(c103.383,60.575) 103.752,60.948 104.742,59.958 ccw(c104.883,60.1) 104.883,59.9 105.76,59.9 105.94,60.08 105.96,60.08 106.16,60.28 C7.2@106.16,60.3
USB3.0_SSTX_N: C6.1 J5.A3 J5.B3 U8.1@109.25,59.6 | length 32
  Top Layer w0.2: C6.1@107.04,59.2 107.24,59.4 107.24,59.47 107.357,59.587 109.362,59.587 U8.1@109.4,59.625 ; U8.1@109.25,59.6 U8.1@109.4,59.625 ; v3(113.199,59.025) 113.259,59.025 113.378,58.906 113.709,58.906 113.716,58.912 114.188,58.912 114.226,58.95 114.65,58.95 J5.A3@114.7,59 ; J5.B3@116,62.75 116.824,62.915 116.927,62.925 118.966,62.925 v3@119.108,62.783 ; v3(117.3,57.77) 117.36,57.77 117.58,57.55 117.635,57.55 117.996,57.188 cw(c117.625,56.817) 118.15,56.817 118.15,56.204 cw(c117.625,56.204) 117.998,55.834 117.996,55.832 117.617,55.453 cw(c117.246,55.825) 117.246,55.3 114.283,55.3 cw(c114.283,55.825) 113.913,55.452 109.786,59.579 ccw(c109.645,59.437) 109.645,59.637 109.519,59.637 ccw(c109.52,59.437) 109.497,59.636 U8.1@109.4,59.625
  Bottom Layer w0.2: v3(113.199,59.025) 113.199,59.017 113.316,58.9 115.242,58.9 cw(c115.242,58.375) 115.612,58.747 116.541,57.818 ccw(c116.93,58.214) 116.955,57.66 116.961,57.66 ccw(c116.942,57.859) 116.997,57.667 117.233,57.736 ccw(c117.177,57.928) v3(117.3,57.77) 117.381,57.77 117.539,57.612 118.129,57.612 ccw(c118.129,57.812) 118.271,57.671 119.442,58.842 ccw(c119.3,58.983) 119.5,58.983 119.5,62.43 119.248,62.682 119.054,62.682 v3(119.012,62.724)
USB3.0_SSTX_P: C7.1 J5.A2 J5.B2 U8.2@109.3,60 | length 31.6
  Top Layer w0.2: C7.1@107.04,60.3 107.24,60.1 107.24,60.03 107.357,59.912 108.869,59.912 108.902,59.945 108.953,59.945 ; 109,59.95 109.083,59.95 109.108,59.975 109.275,59.975 U8.2@109.3,60 109.4,59.975 109.497,59.964 ccw(c109.52,60.162) 109.519,59.962 109.645,59.962 cw(c109.645,59.437) 110.017,59.808 114.142,55.683 ccw(c114.283,55.825) 114.283,55.625 117.246,55.625 ccw(c117.246,55.825) 117.388,55.683 117.767,56.062 ccw(c117.625,56.204) 117.825,56.204 117.825,56.817 ccw(c117.625,56.817) 117.767,56.958 117.672,57.053 117.5,57.225 117.494,57.219 117.31,57.219 v3(117.268,57.177) ; v3(113.199,58.461) 113.259,58.461 113.378,58.581 113.844,58.581 113.851,58.587 114.188,58.587 114.226,58.55 114.65,58.55 J5.A2@114.7,58.5 ; J5.B2@116,63.25 v3@119.25,63.25
  Bottom Layer w0.2: v3(113.199,58.461) 113.203,58.461 113.316,58.575 115.108,58.575 115.242,58.575 cw(c115.242,58.375) 115.384,58.516 116.312,57.588 ccw(c116.93,58.214) 116.315,57.585 ccw(c116.93,58.214) 116.972,57.335 cw(c116.968,57.135) 117.108,57.277 117.152,57.233 ccw(c117.293,57.376) v3(117.268,57.177) 117.325,57.235 117.543,57.235 117.595,57.287 118.129,57.287 ccw(c118.129,57.812) 118.5,57.44 119.673,58.613 ccw(c119.3,58.983) 119.825,58.983 119.825,62.565 119.522,62.868 119.522,62.946 119.388,63.079 v3(119.388,63.139)
VBUS: R13.1 R15.2 U6.34 | length 7.4
  Top Layer w0.2: U6.34@79.541,71.3 80.556,71.3 81.656,70.2 R15.2@84.656,70.2 R13.1@84.656,68.4
VBUS_+5V: C1.2 C2.2 C3.2 C4.2 C5.2 C11.2 C29.2 J2.2@60.8,47.74 J5.A4 J5.A9 J5.B4 J5.B9 R2.2 R3.2 R4.2 R5.2 R6.2@104.9,54 R8.2 R13.2 U1.8 U2.5 U3.5 U4.8 U5.5 U7.4 U7.5 U7.6 U8.3@109.3,60.4 U9.4 U9.5 U9.6 | length 66.6
  Top Layer w0.2: R13.2@85.656,68.4 v1(86.3,68.4) ; U8.3@109.3,60.4 109.4,60.4 110.433,60.4 110.7,60.133 v1(110.7,60.1)
  Top Layer w0.3: v1(84.55,49.7) 84.61,49.76 C3.2@84.61,50.45 83.8,50.45 83.55,50.7 83.55,51.45 84.05,51.95 U1.8@84.725,51.95 ; v1(84.8,54.3) 84.81,54.31 C5.2@84.81,55.15 84,55.15 83.75,55.4 83.75,56.15 84.25,56.65 U4.8@84.925,56.65 ; R8.2@94,60.5 v1(94.8,60.5) ; R2.2@94,61.9 v1(94.75,61.9) ; U3.5@94.9,52.7 95.325,52.73 96.08,52.73 C2.2@96.3,52.81 ; U5.5@94.9,56.7 96.26,56.7 C4.2@96.3,56.74 v1(96.3,57.6) ; C2.2@96.25,52.81 96.42,52.804 v1(97.1,52.8) ; U5.5@101.4,52.7 101.46,52.76 C5.2@102.8,52.76 v1(102.8,51.8) ; U2.5@101.4,56.8 101.43,56.77 102.77,56.77 C1.2@102.8,56.74 102.837,56.777 103.477,56.777 v1(103.5,56.8) ; v1(104.1,49.8) R3.2@104.9,49.8 ; v1(104.1,51.2) R4.2@104.9,51.2 ; v1(104.1,52.6) R5.2@104.9,52.6 ; v1(104.1,54) R6.2@104.9,54 ; U7.6@109.625,68.717 U7.5@109.625,67.767 U7.4@109.625,66.817 109.625,66.342 109.7,66.267 ; v1(113.8,59.5) J5.A4@114.7,59.5 ; v1(113.9,62.5) J5.A9@114.7,62.5 ; J5.B9@116,59.75 116.818,59.75 116.868,59.8 v1(116.9,59.8) ; J5.B4@116,62.25 116.718,62.25 116.768,62.3 v1(116.8,62.3)
  Bottom Layer w0.5: v1(86.3,68.4) 92.981,61.719 93.503,61.719 ccw(c93.503,62.219) 93.577,61.725 v1(94.75,61.9)
  Bottom Layer w1: J2.2@60.8,47.72 66.97,47.72 71.5,52.25 82,52.25 v1(82.5,52.75) v1(83,52.25) v1(82.5,51.75)
  other v2: 111.2,67.267 112.45,67.267 112.45,68.517 111.2,71.517 112.45,71.517 112.45,72.767
VCC_RF: IC1.14 IC2.9 R38.1 | length 10.3
  Top Layer w0.5: IC1.14@73.35,50.6 74.8,50.6 76,49.4 v1(76,48.5) ; R38.1@76.1,42.3 76.1,44.55 IC2.9@76.05,44.6 76.05,46.15 v1(76.1,46.2)
  Bottom Layer w0.5: v1(76,48.5) 76.1,48.4 v1(76.1,46.2)
VCCK10: C28.2 C35.2 C36.2 C37.2 C38.2 L2.2 R32.1 U6.24 U6.30 U6.31 U6.32 U6.57 U6.58 | length 21
  Top Layer w0.2: U6.58@73.991,76.45 73.991,77.135 74.156,77.3 74.391,77.065 U6.57@74.391,76.45 ; v1(76.1,67.3) 76.391,67.591 U6.24@76.391,69.35 ; U6.30@78.791,69.35 78.791,68.665 79.056,68.4 80.333,68.4 80.533,68.6 v1(80.6,68.6) 80.656,68.656 v1@80.656,69.4 ; v1(80.7,69.4) 80.689,69.411 80.689,69.767 80.656,69.8 ; R32.1@101.9,73.017 101.9,70.792 L2.2@101.925,70.767 ; 80.356,70.1 80.656,69.8 ; 80.356,70.1 U6.31@79.541,70.1 U6.32@79.541,70.5 80.256,70.5 80.656,70.1 ; 80.356,70.1 80.656,70.1 ; 80.656,69.8 80.656,70.1
  Top Layer w0.4: C38.2@73.056,79.36 v1(73.056,78.7) 73.06,78.696 73.06,78.396 74.106,77.35 74.106,77.25 ; v1(76.1,67.3) 76.1,67.273 76.256,67.117 C35.2@76.256,66.34
  Top Layer w0.5: v1(80,69.1) 80.056,69.1 80.556,68.6 v1(80.6,68.6) 80.8,68.4 C37.2@82.316,68.4 C36.2@82.316,67.3
  other v2: 84.656,64.9 83.956,65.7 84.656,66.4
  other v5: 100.75,69.417 99.95,70.017 100.7,70.767
VCORE_LDO: C15.2 FB1.1 U6.55 | length 14.2
  Top Layer w0.2: v1(75.056,78.7) 75.056,78.64 74.956,78.54 74.956,77.94 75.191,77.705 U6.55@75.191,76.45
  Top Layer w0.4: v1(75.056,78.7) C15.2@75.056,79.36
  Top Layer w0.5: v1(83.25,79) 83.249,78.47 FB1.1@83.24,78.4 v1(84.1,78.4)
  Bottom Layer w0.5: v1(75.056,78.7) 75.656,79.3 77.956,79.3 78.256,79 83.5,79 v1(84.1,78.4)
XTL20N: R26.2 U6.16 | length 6.3
  Top Layer w0.203: R26.2@70.25,64.75 70.398,64.716 70.882,64.716 ccw(c70.882,64.919) 71.025,64.775 73.132,66.882 ccw(c72.988,67.025) 73.191,67.025 U6.16@73.191,69.35
XTL20P: R25.2 U6.17 | length 7.1
  Top Layer w0.203: R25.2@70.25,63.75 70.416,63.75 ccw(c70.416,63.953) 70.559,63.809 73.532,66.782 ccw(c73.388,66.925) 73.591,66.925 U6.17@73.591,69.35
pads on no net: IC1.5 IC1.6 IC1.9 IC1.13 IC1.15 IC2.4 IC2.5 IC2.6 IC2.8 IC2.14 IC2.15 IC2.16 IC2.17 IC2.22 J3.MH3 J3.MH4 J3.P9 J5.A8 J5.B8 MNT1. MNT2. MNT3. MNT4. U6.18 U6.22 U6.47 U6.48 U6.49 U6.60 U8.9@108.625,61.58 U8.10

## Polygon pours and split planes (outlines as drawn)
GND on Top Layer "NONET_L-01_P-001" (solid, pour order 62): 59,82 103.7,82 110.7,75 120,75 120,47 110.7,47 103.7,40 59,40
GND on Top Layer "NONET_L-01_P-001" (solid, pour order 67): 52.3,67.9 52.4,67.9 53.8,66.5 58.55,66.5 59.55,65.5 59.55,76 58.8,75.25 52.3,75.25 52.3,74.5
NetC17_2 on Top Layer "NONET_L-01_P-001" (solid, pour order 57): 68.95,69.45 70.7,69.45 71.45,70.2 72.8,70.2 72.8,69.55 71.2,67.95 71.2,67.2 70.95,66.95 69.2,66.95 68.95,67.2
VCCK10 on Top Layer "NONET_L-01_P-001" (solid, pour order 56): 82.5,64.25 81.25,65.5 81.25,66.75 79.75,68.25 79,68.25 78.5,68.75 78.5,70.5 78.75,70.75 80.25,70.75 82.5,68.5 82.5,67.25 82.9,66.85 84.8,66.85 85.1,66.55 85,66.45 85,64.65 84.6,64.25
NetL1_1 on Top Layer "NONET_L-01_P-001" (solid, pour order 52): 106.25,67.25 104.75,68.75 104,68.75 103.75,68.5 103.75,66.5 104.25,66 106.75,66 107.25,66.5 107.25,67 107,67.25
NetL2_1 on Top Layer "NONET_L-01_P-001" (solid, pour order 51): 103.65,71.55 104.15,72.05 105.15,72.05 105.65,71.55 106.95,71.55 107.15,71.35 107.15,70.35 106.55,69.75 103.95,69.75 103.65,70.05
VBUS_+5V on Top Layer "NONET_L-01_P-001" (solid, pour order 50): 109,68.75 109.5,69.25 112.5,69.25 113,68.75 113,66.25 112.5,65.75 109.5,65.75 109,66.25
VBUS_+5V on Top Layer "NONET_L-01_P-001" (solid, pour order 49): 109,73.25 109.5,73.75 112.5,73.75 113,73.25 113,70.75 112.5,70.25 109.5,70.25 109,70.75
VCCK10 on Top Layer "NONET_L-01_P-001" (solid, pour order 53): 102.725,72.433 99.225,72.433 99.225,69.383 99.675,68.933 101.725,68.933 102.725,69.933
DVDD_33 on Top Layer "NONET_L-01_P-001" (solid, pour order 54): 99.7,65.183 99.2,65.683 99.225,68.683 102.725,68.683 102.725,65.683 102.225,65.183 99.725,65.183
CHASSIS_GND on Top Layer "NONET_L-01_P-001" (solid, pour order 63): 51.3,71 51.8,71.5 51.8,74.75 51.55,75 47.8,75 47.3,74.5 47.3,52 47.8,51.5 50.8,51.5 51.3,52
DVDD_33 on Int2 "NONET_L-01_P-001" (solid, pour order 68): 102.5,66 100,63.5 92,63.5 81.5,53 81.5,40 57,40 57.5,40.5 57.5,53.5 66.5,62.5 66.5,82 86.75,82 100,82 102.5,79.5
VBUS_+5V on Int2 "NONET_L-01_P-001" (solid, pour order 70): 103.3,75 117.8,75 117.8,71 117.8,56 116.8,55 110.8,55 104.8,49 81.8,49 81.8,53 91.8,63 100.3,63 103.3,66
VCCK10 on Int2 "NONET_L-01_P-001" (solid, pour order 60): 83,64 85,64 89.5,68.5 101.5,68.5 102.5,69.5 102.5,72 101.5,73 89,73 83.3,67.3 82.5,66.5 82.5,64.5
VCCK10 on Int2 "NONET_L-01_P-001" (solid, pour order 61): 72.85,79.05 73.25,79.05 74.1,78.2 79.7,78.2 82.1,75.8 82.1,69.6 80.5,68 77.9,68 77.85,68.05 76.6,68.05 76.35,67.8 76.35,67.05 75.6,66.3 74.1,66.3 72.6,67.8 72.6,74.3 71.1,75.8 71.1,77.8 71.6,78.3 72.1,78.3
GND on Int1 "NONET_L-01_P-001" (solid, pour order 65): 59,82 103.2,82 110.2,75 119.7,75 119.7,47 110.2,47 103.2,40 59,40
CHASSIS_GND on Int1 "NONET_L-01_P-001" (solid, pour order 64): 47.3,74.5 47.8,75 50.8,75 51.3,74.5 51.3,52 50.8,51.5 47.8,51.5 47.3,52
GND on Bottom Layer "NONET_L-01_P-001" (solid, pour order 66): 59,75.25 58.5,74.75 52,74.75 52,67.5 53.5,66 58.25,66 59,65.25 59,40 101.5,40 108.5,47 120,47 120,75 108.5,75 101.5,82 59,82
DVDD_1.85 on Bottom Layer "NONET_L-01_P-001" (solid, pour order 59): 73.6,76.2 78.1,76.2 79.1,75.2 79.1,71.7 77.1,69.7 77.1,67.2 77.6,66.7 77.6,66.2 79.1,66.2 81.6,68.7 81.6,72.7 81.1,73.2 81.1,78.5 79.1,78.5 78.4,79.2 73.6,79.2 73.1,78.7 73.1,76.7

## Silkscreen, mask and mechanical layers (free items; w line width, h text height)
Top Overlay:
  lines w0.3: 62.95,69.3 62.95,57.3 63.45,59.3 62.95,59.3 63.2,59.05 63.2,58.55
  text "PPS" at 58.5,67.2 h3
  text "TX" at 58.5,64.7 h3
  text "PPS" at 88,63.8 h3
  text "RX" at 58.5,62.2 h3
  text "OUT" at 88,61.6 h3
  text "+5V" at 58.5,59.7 h3
  text "IN" at 88,59.4 h3
  text "SCL" at 69.25,58.9 h3
  text "SDA" at 78.75,58.9 h3
  text "GND" at 58.5,57.2 h3
  text "1->4" at 115.3,49.2 h3 r90
  text "ANT" at 90.6,42.5 h3 r90
  text "PPS" at 93.1,42.5 h3 r90
Mechanical 19:
  drawing of 176 lines, arcs and shapes, not listed

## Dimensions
50,75 to 40,75 on Top Component Center
110,75 to 122,75 on Top Component Center
55,78.5 to 55,43.5 on Top Component Center
55,43.5 to 105,43.5 on Top Component Center
122,47 to 122,75 on Top Component Center
50,82 to 110,82 on Top Component Center
110,40 to 103.7,82 on Top Component Center
40,75 to 122,75 on Top Component Center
